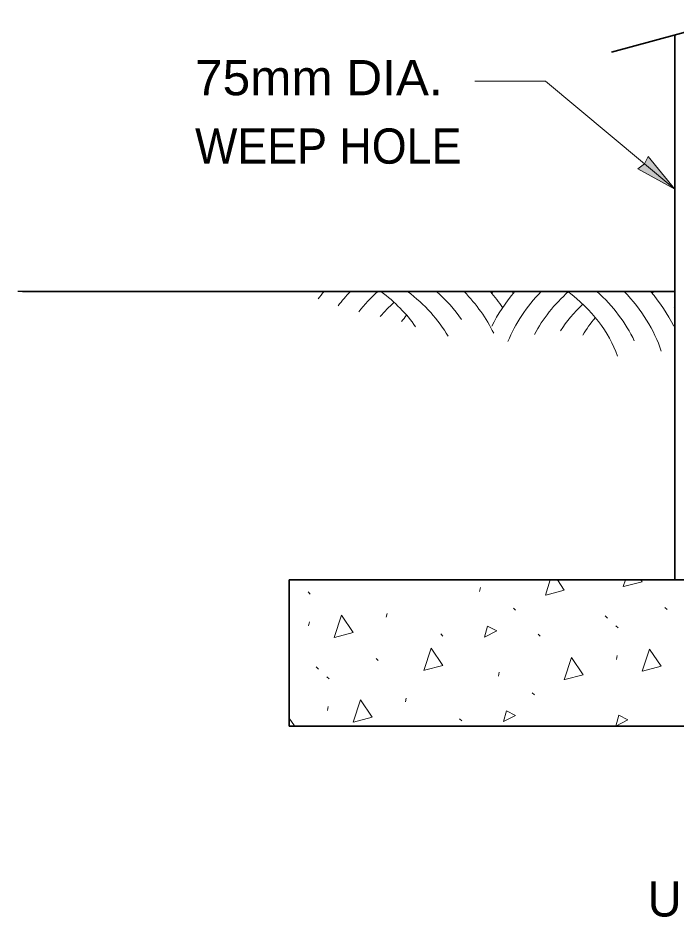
# Model space of a CAD drawing. Extents: x 17672 to 18472, y -9785 to -9267.
# Drawn here: x 18030.2 to 18096, y -9424.3 to -9334.3 of the extents above; entities that cross this region are included whole.
import ezdxf

# ---------------------------------------------------------------- set-up
doc = ezdxf.new("R2010")
doc.units = 0
doc.header["$LTSCALE"] = 1.4
for name, color, linetype, lineweight in [('1', 7, 'Continuous', 13), ('15', 7, 'Continuous', 13), ('16', 7, 'Continuous', 13), ('20', 7, 'Continuous', 25)]:
    doc.layers.add(name, color=color, linetype=linetype, lineweight=lineweight)
doc.layers.add('19', color=7, linetype='Continuous')

msp = doc.modelspace()

# ---------------------------------------------------------------- hatches: boundary and pattern name
at = {"layer": '16'}
msp.add_hatch(color=256, dxfattribs=at).paths.add_polyline_path([(18095.944, -9351.462), (18093.268, -9348.212), (18092.91, -9348.932), (18092.241, -9349.442)])

# ---------------------------------------------------------------- linework, layer by layer
at = {"layer": '1', "lineweight": 35}
for p, q in [((18089.594, -9337.743), (18102.143, -9334.332)), ((18095.915, -9390.572), (18095.915, -9336.025)), ((18095.915, -9361.729), (18030.635, -9361.729))]:
    msp.add_line(p, q, dxfattribs=at)
at = {"layer": '1', "lineweight": 25}
for p, q in [((18095.915, -9361.729), (18030.194, -9361.729)), ((18095.878, -9363.278), (18095.915, -9363.337)), ((18095.964, -9365.222), (18095.939, -9364.981))]:
    msp.add_line(p, q, dxfattribs=at)
at = {"layer": '1'}
for p, q in [((18095.947, -9377.768), (18095.954, -9377.751)), ((18095.947, -9379.003), (18095.954, -9378.986)), ((18095.949, -9378.606), (18095.952, -9378.621)), ((18095.947, -9380.239), (18095.954, -9380.224)), ((18095.949, -9379.839), (18095.952, -9379.856)), ((18082.976, -9392.121), (18083.471, -9390.594)), ((18090.76, -9391.268), (18090.979, -9390.594)), ((18059.228, -9391.8), (18059.439, -9392.013)), ((18076.376, -9391.746), (18076.478, -9391.349)), ((18079.782, -9393.423), (18079.976, -9393.638)), ((18094.947, -9393.356), (18095.158, -9393.572)), ((18067.057, -9394.332), (18067.147, -9393.955)), ((18088.966, -9394.192), (18089.18, -9394.42)), ((18059.275, -9395.185), (18059.363, -9394.793)), ((18090.037, -9395.182), (18090.248, -9395.396)), ((18072.508, -9396.008), (18072.719, -9396.224)), ((18082.251, -9396.021), (18082.461, -9396.234)), ((18090.084, -9398.567), (18090.172, -9398.173)), ((18066.025, -9398.457), (18066.236, -9398.67)), ((18060.044, -9399.29), (18060.258, -9399.521)), ((18078.277, -9400.224), (18078.366, -9399.832)), ((18061.116, -9400.281), (18061.326, -9400.494)), ((18068.961, -9402.81), (18069.049, -9402.418)), ((18081.67, -9401.903), (18081.878, -9402.104)), ((18061.162, -9403.665), (18061.25, -9403.273)), ((18074.395, -9404.491), (18074.606, -9404.705))]:
    msp.add_line(p, q, dxfattribs=at)
at = {"layer": '1', "lineweight": 35}
msp.add_lwpolyline([(18095.915, -9390.594), (18057.336, -9390.594), (18057.336, -9405.234), (18148.839, -9405.234), (18148.839, -9390.594), (18120.263, -9390.594)], close=True, dxfattribs=at)
at = {"layer": '1'}
for points in [[(18084.175, -9390.594), (18084.868, -9391.616), (18083.023, -9392.114)], [(18092.545, -9390.594), (18092.667, -9390.776), (18090.805, -9391.261)], [(18120.263, -9390.594), (18095.915, -9390.594), (18095.915, -9390.572)], [(18061.839, -9396.366), (18062.562, -9394.133), (18063.748, -9395.874), (18061.885, -9396.359)], [(18070.824, -9399.653), (18071.547, -9397.42), (18072.716, -9399.146), (18070.871, -9399.646)], [(18092.665, -9399.746), (18093.385, -9397.513), (18094.555, -9399.239), (18092.694, -9399.741)], [(18084.863, -9400.587), (18085.584, -9398.354), (18086.77, -9400.094), (18084.907, -9400.58)], [(18063.743, -9404.844), (18064.464, -9402.611), (18065.633, -9404.337), (18063.772, -9404.839)], [(18057.336, -9404.44), (18057.851, -9405.192), (18057.692, -9405.234)], [(18090.035, -9405.234), (18090.329, -9404.148), (18091.241, -9404.599), (18090.04, -9405.234)]]:
    msp.add_lwpolyline(points, dxfattribs=at)
for points in [[(18076.898, -9396.32), (18077.192, -9395.229), (18078.108, -9395.697)], [(18078.785, -9404.786), (18079.096, -9403.707), (18079.993, -9404.163)]]:
    msp.add_lwpolyline(points, close=True, dxfattribs=at)
for centre, major_axis, start_param, end_param in [((18083.6, -9371.721), (-26.675, 0), 5.734425, 5.779681), ((18083.6, -9371.721), (-24.471, 0), 5.678359, 5.774233), ((18083.6, -9371.721), (-22.266, 0), 5.608166, 5.761688), ((18052.059, -9371.721), (20.062, 0), 0.464937, 0.765516), ((18054.71, -9371.721), (20.062, 0), 0.393014, 0.765516), ((18054.71, -9371.721), (22.266, 0), 0.466922, 0.675019), ((18054.71, -9371.721), (24.471, 0), 0.336904, 0.604826), ((18054.71, -9371.721), (26.675, 0), 0.453104, 0.54876), ((18102.687, -9371.721), (-26.675, 0), 5.734425, 5.935901), ((18056.728, -9347.969), (28.469, 0), 5.536005, 5.547483), ((18102.687, -9371.721), (-24.471, 0), 5.678359, 5.994746), ((18100.668, -9347.969), (-28.469, 0), 0.735703, 0.74718), ((18102.687, -9371.721), (-22.266, 0), 5.608166, 5.918958), ((18070.744, -9371.721), (20.062, 0), 0.247668, 0.765516), ((18070.744, -9371.721), (22.266, 0), 0.321019, 0.675019), ((18070.744, -9371.721), (24.471, 0), 0.230357, 0.604826), ((18070.744, -9371.721), (26.675, 0), 0.346641, 0.54876), ((18072.763, -9347.969), (28.469, 0), 5.536005, 5.547483), ((18083.6, -9371.721), (-20.062, 0), 5.616853, 5.737693), ((18102.687, -9371.721), (-20.062, 0), 5.633205, 5.850148), ((18086.065, -9371.79), (-20.062, 0), 5.720851, 5.771052), ((18105.152, -9371.79), (-20.062, 0), 5.740022, 5.87774)]:
    msp.add_ellipse(centre, major_axis=major_axis, ratio=0.719298, start_param=start_param, end_param=end_param, dxfattribs=at)
at = {"layer": '15'}
for p, q in [((18082.996, -9340.667), (18075.927, -9340.667)), ((18095.944, -9351.462), (18082.996, -9340.667))]:
    msp.add_line(p, q, dxfattribs=at)
at = {"layer": '16'}
msp.add_lwpolyline([(18095.944, -9351.462), (18093.268, -9348.212), (18092.91, -9348.932), (18092.241, -9349.442)], close=True, dxfattribs=at)

# ---------------------------------------------------------------- texts
at = {"layer": '19'}
for s, width, p in [('75mm DIA.', 1.05, (18047.919, -9342.069)), ('WEEP HOLE', 0.95, (18047.919, -9348.92))]:
    msp.add_text(s, height=3.529, dxfattribs=dict(at, width=width)).set_placement(p)
at = {"layer": '20'}
msp.add_text('UNDERDRAIN PIPE', height=3.529, dxfattribs=at).set_placement((18093.204, -9424.295))

doc.saveas('drawing.dxf')
